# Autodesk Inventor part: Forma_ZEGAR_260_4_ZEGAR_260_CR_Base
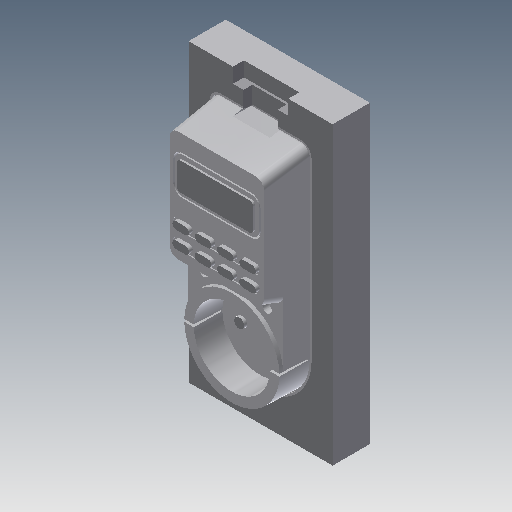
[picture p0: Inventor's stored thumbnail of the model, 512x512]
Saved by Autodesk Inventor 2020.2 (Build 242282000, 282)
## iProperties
Created: 2015-01
Part Number: Forma_ZEGAR_260_4_ZEGAR_260_CR_Base
Material: Ogólny
Document SubType Name: Modeling
Designer: F.Stasiak
Density: 1 g/cm^3
Appearance: Domyślna
Catalog Web Link: www.expertbooks.pl
Manager: www.cadconsulting.pl
Company: Fabian Stasiak CAD Consulting
Author: F.Stasiak
Subject: Zbiór ćwiczeń. Autodesk Inventor 2020. Kurs Professional
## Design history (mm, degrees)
node "Forma_ZEGAR_260_4_ZEGAR_260_MP"
feature "Rzeźbienie1"
feature "Bryła3::Forma_ZEGAR_260_4_ZEGAR_260_MP"
tag "Bryła wyprowadzona1"
node "Bryła1"
feature "Forma_ZEGAR_260_4_ZEGAR_260_MP_Bodies"
feature "Powierzchnia1"
body "Srf1"
